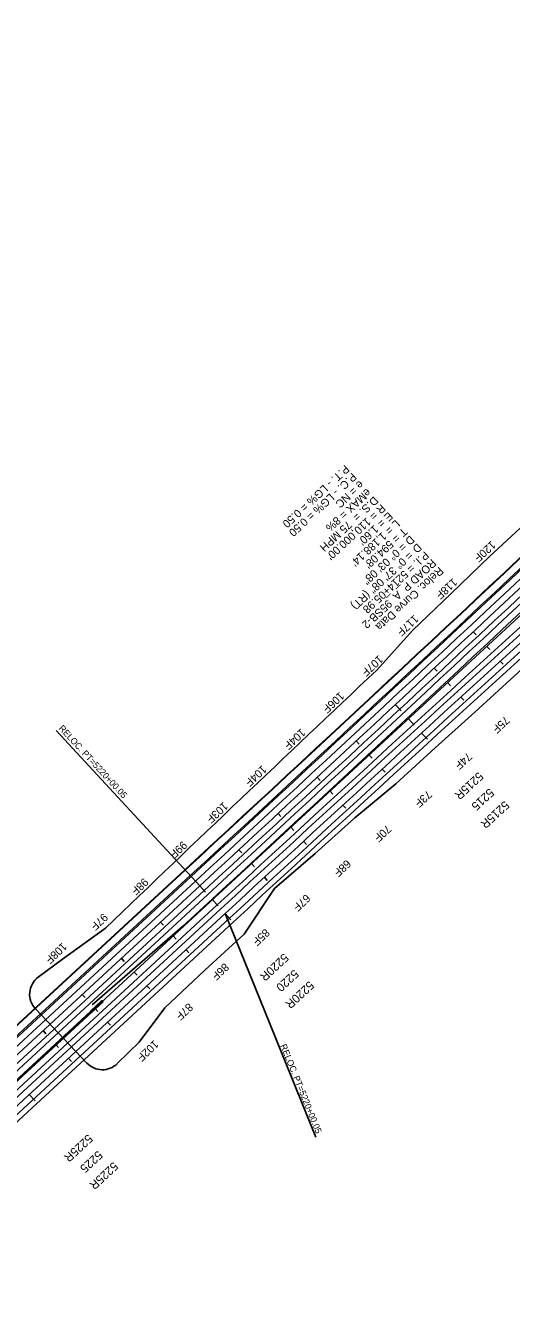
# Model space of a CAD drawing. Extents: x 2160876 to 2175625, y 601634 to 617693.
# Drawn here: x 2168332 to 2169242, y 609675 to 612093 of the extents above; entities that cross this region are included whole.
import ezdxf

# ---------------------------------------------------------------- set-up
doc = ezdxf.new("R2010")
doc.units = 0
for name, color, linetype in [('RD_HC_Cl', 7, 'Continuous'), ('RD_HC_CL_Rel', 7, 'Continuous'), ('RD_HC_Data_Rel', 7, 'Continuous'), ('RD_HC_Data_Tic', 7, 'Continuous'), ('RD_HC_Data_Tic_Rel', 7, 'Continuous'), ('RD_HC_TX_Rel_Sta50', 7, 'Continuous'), ('RD_HC_TX_Sta50', 7, 'Continuous'), ('RD_PD_CstnLmt', 7, 'Continuous'), ('RD_PD_Final_LnLine', 7, 'Continuous'), ('RD_PD_Final_TrvlWay', 7, 'Continuous'), ('RD_PD_GR', 7, 'Continuous'), ('RD_PD_MedBWall', 7, 'Continuous'), ('RD_PD_MedGR', 7, 'Continuous')]:
    doc.layers.add(name, color=color, linetype=linetype)

msp = doc.modelspace()

# ---------------------------------------------------------------- linework, layer by layer
at = {"layer": 'RD_HC_Cl'}
msp.add_line((2172239.9, 613739.9), (2163704.8, 605858.6), dxfattribs=at)
at = {"layer": 'RD_HC_CL_Rel'}
for p, q in [((2168658.1, 610480.3), (2165572.4, 607631)), ((2168705.8, 610428.6), (2165620.1, 607579.3))]:
    msp.add_line(p, q, dxfattribs=at)
for centre, start, end in [((2094033.1, 691295.6), 312.719474, 313.338342), ((2243330.9, 529613.4), 132.100607, 132.719474)]:
    msp.add_arc(centre, 110000, start, end, dxfattribs=at)
at = {"layer": 'RD_HC_Data_Rel'}
for p, q in [((2168658.1, 610480.3), (2168389, 610771.7)), ((2168705.8, 610428.6), (2168876, 610009.4))]:
    msp.add_line(p, q, dxfattribs=at)
at = {"layer": 'RD_HC_Data_Tic'}
for p, q in [((2169196.2, 610929.4), (2169201.7, 610923.5)), ((2169122.8, 610861.5), (2169128.2, 610855.6)), ((2169049.3, 610793.7), (2169060.2, 610781.9)), ((2168975.8, 610725.8), (2168981.3, 610720)), ((2168902.4, 610658), (2168907.8, 610652.1)), ((2168828.9, 610590.2), (2168834.3, 610584.3)), ((2168755.4, 610522.3), (2168760.9, 610516.4)), ((2168682, 610454.5), (2168692.8, 610442.7)), ((2168608.5, 610386.6), (2168613.9, 610380.8)), ((2168535, 610318.8), (2168540.5, 610312.9)), ((2168461.6, 610251), (2168467, 610245.1)), ((2168388.1, 610183.1), (2168393.5, 610177.2))]:
    msp.add_line(p, q, dxfattribs=at)
at = {"layer": 'RD_HC_Data_Tic_Rel'}
for p, q in [((2169170.9, 610956.9), (2169176.4, 610951)), ((2169097.8, 610888.6), (2169103.3, 610882.7)), ((2169221.6, 610901.9), (2169227, 610896)), ((2169147.8, 610834.5), (2169153.2, 610828.6)), ((2169024.7, 610820.4), (2169035.6, 610808.7)), ((2169074, 610767), (2169084.8, 610755.2)), ((2168951.5, 610752.2), (2168957, 610746.4)), ((2169000.2, 610699.5), (2169005.6, 610693.6)), ((2168878.3, 610684.2), (2168883.7, 610678.3)), ((2168804.9, 610616.2), (2168810.4, 610610.3)), ((2168926.5, 610631.9), (2168931.9, 610626)), ((2168731.6, 610548.2), (2168737, 610542.3)), ((2168852.9, 610564.2), (2168858.3, 610558.3)), ((2168779.4, 610496.5), (2168784.8, 610490.6)), ((2168658.1, 610480.3), (2168669, 610468.6)), ((2168705.9, 610428.7), (2168716.7, 610416.9)), ((2168584.7, 610412.5), (2168590.1, 610406.6)), ((2168632.4, 610360.8), (2168637.8, 610355)), ((2168511.2, 610344.7), (2168516.6, 610338.8)), ((2168437.7, 610276.8), (2168443.2, 610270.9)), ((2168558.9, 610293), (2168564.3, 610287.1)), ((2168364.3, 610209), (2168369.7, 610203.1)), ((2168485.4, 610225.1), (2168490.9, 610219.3)), ((2168412, 610157.3), (2168417.4, 610151.4)), ((2168338.5, 610089.5), (2168349.4, 610077.7))]:
    msp.add_line(p, q, dxfattribs=at)
at = {"layer": 'RD_PD_CstnLmt'}
for p, q in [((2169275, 611166.3), (2169201.5, 611098.2)), ((2169201.5, 611098.2), (2169129.7, 611028.4)), ((2169129.7, 611028.4), (2169057, 610959.4)), ((2169057, 610959.4), (2168989.9, 610884.6)), ((2168446.6, 610148.2), (2168350.2, 610249.6)), ((2168544.5, 610187.1), (2168503.5, 610147.1))]:
    msp.add_line(p, q, dxfattribs=at)
for points in [[(2169947.4, 611516.2), (2169906.8, 611486.5), (2169832.2, 611419.8), (2169766.1, 611344.1), (2169692.9, 611276), (2169621.4, 611206), (2169538.3, 611148.5), (2169467, 611078.3), (2169391.8, 611012.4), (2169318.6, 610944.2), (2169284.7, 610907.2), (2169174, 610806.1), (2169099.5, 610739.3), (2169025.5, 610672), (2168948.7, 610607.8), (2168874.4, 610540.9), (2168798.4, 610475.8), (2168741.5, 610390), (2168667.6, 610322.7), (2168592.4, 610252), (2168544.5, 610187.1)], [(2168481.4, 610401.1), (2168400.7, 610342.8), (2168355.4, 610309.3)]]:
    msp.add_lwpolyline(points, dxfattribs=at)
for centre, radius, start, end in [((2219097.5, 557675.8), 73088.7, 133.280708, 133.830736), ((2168379.2, 610277.1), 40, 126.5043, 223.5367), ((2168475.6, 610175.7), 40, 223.5367, 314.3005)]:
    msp.add_arc(centre, radius, start, end, dxfattribs=at)
at = {"layer": 'RD_PD_Final_LnLine'}
for p, q in [((2168630.1, 610510.7), (2165544.4, 607661.4)), ((2168630.7, 610509.9), (2165545.1, 607660.6)), ((2168650, 610489.1), (2165564.3, 607639.8)), ((2168658.1, 610480.3), (2165572.4, 607631)), ((2168666.2, 610471.5), (2165580.6, 607622.2)), ((2168697.7, 610437.5), (2165612, 607588.1)), ((2168705.8, 610428.6), (2165620.1, 607579.3)), ((2168714, 610419.8), (2165628.3, 607570.5))]:
    msp.add_line(p, q, dxfattribs=at)
for centre, radius, start, end in [((2094033.1, 691295.6), 109958.7, 312.719474, 313.338342), ((2094033.1, 691295.6), 109959.7, 312.719474, 313.338342), ((2094033.1, 691295.6), 109988, 312.719474, 313.338342), ((2094033.1, 691295.6), 110000, 312.719474, 313.338342), ((2094033.1, 691295.6), 110012, 312.719474, 313.338342), ((2243330.9, 529613.4), 110012, 132.100607, 132.719474), ((2243330.9, 529613.4), 110000, 132.100607, 132.719474), ((2243330.9, 529613.4), 109988, 132.100607, 132.719474)]:
    msp.add_arc(centre, radius, start, end, dxfattribs=at)
at = {"layer": 'RD_PD_Final_TrvlWay'}
for p, q in [((2168641.8, 610497.9), (2165556.1, 607648.6)), ((2168673, 610464.1), (2165587.4, 607614.8)), ((2168690.9, 610444.8), (2165605.2, 607595.5)), ((2168720.7, 610412.5), (2165635.1, 607563.2))]:
    msp.add_line(p, q, dxfattribs=at)
for centre, radius, start, end in [((2094033.1, 691295.6), 109976, 312.719474, 313.338342), ((2094033.1, 691295.6), 110022, 312.719474, 313.338342), ((2243330.9, 529613.4), 110022, 132.100607, 132.719474), ((2243330.9, 529613.4), 109978, 132.100607, 132.719474)]:
    msp.add_arc(centre, radius, start, end, dxfattribs=at)
at = {"layer": 'RD_PD_GR'}
for p, q in [((2168681.2, 610455.3), (2168625.9, 610404.3)), ((2168625.9, 610404.3), (2168456.6, 610257.5))]:
    msp.add_line(p, q, dxfattribs=at)
msp.add_arc((2094033.1, 691295.6), 110034, 312.719474, 313.338342, dxfattribs=at)
at = {"layer": 'RD_PD_MedBWall'}
for p, q in [((2168640.2, 610499.7), (2165554.6, 607650.3)), ((2168641.8, 610497.9), (2165556.1, 607648.6)), ((2168454, 610245.6), (2165100.2, 607148.7)), ((2168455.6, 610243.9), (2165101.8, 607146.9)), ((2168455.6, 610243.9), (2168454, 610245.6))]:
    msp.add_line(p, q, dxfattribs=at)
for radius in [109973.7, 109976]:
    msp.add_arc((2094033.1, 691295.6), radius, 312.719474, 313.338342, dxfattribs=at)
at = {"layer": 'RD_PD_MedGR'}
for p, q in [((2168453.7, 610246), (2168473.5, 610264.3)), ((2168453.7, 610246), (2168473.5, 610264.3)), ((2168456, 610243.5), (2168475.8, 610261.8)), ((2168475.8, 610261.8), (2168456, 610243.5)), ((2168457, 610248.3), (2168473.9, 610263.9)), ((2168458.6, 610246.6), (2168475.5, 610262.2)), ((2168462.8, 610253.7), (2168460.9, 610252)), ((2168463.1, 610254), (2168462.8, 610253.7)), ((2168464.4, 610252), (2168462.8, 610253.7)), ((2168465.1, 610255.8), (2168463.1, 610254)), ((2168464.7, 610252.3), (2168463.1, 610254)), ((2168465.3, 610256), (2168465.1, 610255.8)), ((2168466.6, 610254.1), (2168465.1, 610255.8)), ((2168467.3, 610257.8), (2168465.3, 610256)), ((2168466.9, 610254.3), (2168465.3, 610256)), ((2168467.5, 610258.1), (2168467.3, 610257.8)), ((2168468.8, 610256.1), (2168467.3, 610257.8)), ((2168469.5, 610259.8), (2168467.5, 610258.1)), ((2168469.1, 610256.4), (2168467.5, 610258.1)), ((2168469.8, 610260.1), (2168469.5, 610259.8)), ((2168471, 610258.1), (2168469.5, 610259.8)), ((2168471.7, 610261.9), (2168469.8, 610260.1)), ((2168471.3, 610258.4), (2168469.8, 610260.1)), ((2168473.2, 610260.2), (2168471.7, 610261.9)), ((2168473.5, 610260.4), (2168472, 610262.1)), ((2168475.8, 610261.8), (2168473.5, 610264.3)), ((2168473.8, 610264), (2168473.5, 610264.3)), ((2168475.8, 610261.8), (2168475.5, 610262.1)), ((2168453.7, 610246), (2168454, 610245.6)), ((2168454, 610245.6), (2168453.7, 610246)), ((2168454, 610245.6), (2168457, 610248.3)), ((2168457, 610248.3), (2168454, 610245.6)), ((2168455.6, 610243.9), (2168458.6, 610246.6)), ((2168455.6, 610243.9), (2168458.6, 610246.6)), ((2168456, 610243.5), (2168455.6, 610243.9)), ((2168456, 610243.5), (2168455.6, 610243.9)), ((2168458.4, 610249.7), (2168457, 610248.3)), ((2168458.6, 610246.6), (2168457, 610248.3)), ((2168458.7, 610249.9), (2168458.4, 610249.7)), ((2168460, 610248), (2168458.4, 610249.7)), ((2168460.6, 610251.7), (2168458.7, 610249.9)), ((2168460.3, 610248.2), (2168458.7, 610249.9)), ((2168460.9, 610252), (2168460.6, 610251.7)), ((2168462.2, 610250), (2168460.6, 610251.7)), ((2168462.5, 610250.3), (2168460.9, 610252))]:
    msp.add_line(p, q, dxfattribs=at)
for points in [[(2168458.6, 610246.6), (2168460, 610248), (2168460.3, 610248.2), (2168462.2, 610250), (2168462.5, 610250.3), (2168464.4, 610252), (2168464.7, 610252.3), (2168466.6, 610254.1), (2168466.9, 610254.3), (2168468.8, 610256.1), (2168469.1, 610256.4), (2168471, 610258.1), (2168471.3, 610258.4), (2168473.2, 610260.2), (2168473.5, 610260.4), (2168475.5, 610262.2)], [(2168473.9, 610263.9), (2168472, 610262.1), (2168471.7, 610261.9)], [(2168473.5, 610264.3), (2168473.8, 610264), (2168473.9, 610263.9)], [(2168475.5, 610262.2), (2168475.5, 610262.1), (2168475.8, 610261.8)]]:
    msp.add_lwpolyline(points, dxfattribs=at)
for radius in [1.67, 1.67, 1.27, 1.27]:
    msp.add_arc((2168474.7, 610263.1), radius, 312.7195, 132.7195, dxfattribs=at)

# ---------------------------------------------------------------- texts
at = {"layer": 'RD_HC_Data_Rel'}
for s, height, rotation, p in [('P.T. - LG% = 0.50', 15, 222.7195, (2168930.3, 611270.6)), ('P.C. - LG% = 0.50', 15, 222.7195, (2168943.8, 611255.9)), ('eMAX = 8%', 15, 222.7195, (2168971, 611226.5)), ('e = NC', 15, 222.7195, (2168957.4, 611241.2)), ('D.S. =  75 MPH', 15, 222.7195, (2168984.5, 611211.8)), ("R = 110,000.00'", 15, 222.7195, (2168998.1, 611197.1)), ("E = 1.60'", 15, 222.7195, (2169011.7, 611182.4)), ("L = 1,188.14'", 15, 222.7195, (2169025.2, 611167.8)), ("T = 594.08'", 15, 222.7195, (2169038.8, 611153.1)), ('D = 0° 03\' 08"', 15, 222.7195, (2169052.4, 611138.4)), ('D', 15, 222.7195, (2169066, 611123.7)), ('    = 0° 37\' 08" (RT)', 15, 222.7195, (2169066, 611123.7)), ('P.I. = 5214+05.98', 15, 222.7195, (2169079.5, 611109)), ('ROAD P_A_95SB-2', 15, 222.7195, (2169093.1, 611094.3)), ('Reloc. Curve Data', 15, 222.7195, (2169106.7, 611079.6)), ('RELOC. PT=5220+00.05', 12, 312.7195, (2168392.8, 610775.1)), ('RELOC. PT=5220+00.05', 12, 292.0972, (2168808.8, 610181))]:
    msp.add_text(s, height=height, rotation=rotation, dxfattribs=at).set_placement(p)
at = {"layer": 'RD_HC_TX_Rel_Sta50'}
for s, rotation, p in [('5215R', 222.9799, (2169180.8, 610695.2)), ('5215R', 222.459, (2169229.6, 610641)), ('5220R', 222.7195, (2168815.8, 610354.9)), ('5220R', 222.7194, (2168863.5, 610303.2)), ('5225R', 222.7195, (2168448.5, 610015.7)), ('5225R', 222.7195, (2168496.2, 609964))]:
    msp.add_text(s, height=16, rotation=rotation, dxfattribs=at).set_placement(p)
at = {"layer": 'RD_HC_TX_Sta50'}
for s, p in [('5215', (2169201, 610664.3)), ('5220', (2168834.8, 610324.6)), ('5225', (2168467.1, 609985))]:
    msp.add_text(s, height=16, rotation=222.7195, dxfattribs=at).set_placement(p)
at = {"layer": 'RD_PD_CstnLmt'}
for s, rotation, p in [('120F', 222.5949, (2169204.7, 611128.2)), ('118F', 222.6733, (2169132.8, 611058.4)), ('117F', 222.7518, (2169060.1, 610989.5)), ('107F', 222.8303, (2168993.6, 610913.9)), ('106F', 222.9088, (2168920.7, 610845.2)), ('75F', 222.7518, (2169230.7, 610799.6)), ('104F', 222.9873, (2168847.9, 610776.4)), ('74F', 222.8303, (2169160.1, 610731.5)), ('104F', 223.0658, (2168775.2, 610707.5)), ('73F', 222.9088, (2169084.9, 610660.6)), ('103F', 223.1443, (2168702.6, 610638.6)), ('70F', 222.9873, (2169008.8, 610595.8)), ('99F', 223.2228, (2168626, 610565.6)), ('68F', 223.0658, (2168933.2, 610530.6)), ('98F', 223.3012, (2168553.5, 610496.4)), ('67F', 223.1443, (2168857.1, 610465.9)), ('97F', 223.3797, (2168477.4, 610430.2)), ('85F', 223.2228, (2168780.8, 610401.3)), ('108F', 223.4582, (2168400.7, 610375.2)), ('86F', 223.3012, (2168704.4, 610336.8)), ('87F', 223.3797, (2168636.9, 610261.7)), ('102F', 223.4582, (2168572.4, 610192.2))]:
    msp.add_text(s, height=15, rotation=rotation, dxfattribs=at).set_placement(p)

doc.saveas('drawing.dxf')
